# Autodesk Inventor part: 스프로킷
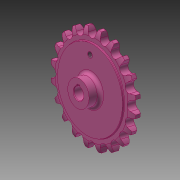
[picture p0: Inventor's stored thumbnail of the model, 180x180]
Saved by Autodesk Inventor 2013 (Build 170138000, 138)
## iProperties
Created: 2016-03
Part Number: 스프로킷
Material: 강철, 탄소
Document SubType Name: Modeling
Designer: mduedu
Density: 7.87 g/cm^3
Mass: 371.373 g
Surface Area: 144.258 cm^2
Volume: 47.1885 cm^3
Author: mduedu
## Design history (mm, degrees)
sketch "스케치1"
  geometry: L1 (0, 5)-(33.5, 5); L2 (33.5, 5)-(33.5, 4.1); L3 (34, 3.6)-(37.625, 3.6); L4 (44, 2)-(44, 0); L5 (44, 0)-(0, 0); L6 (0, 0)-(0, 5); L7 (0, -5)-(33.5, -5); L8 (33.5, -5)-(33.5, -4.1); L9 (34, -3.6)-(37.625, -3.6); L10 (44, -2)-(44, 0); L11 (0, 0)-(0, -5); A1 r 13.5 centre (37.625, -9.9) between (44, 2) and (37.625, 3.6); A2 r 13.5 centre (37.625, 9.9) between (37.625, -3.6) and (44, -2); A3 r 0.5 centre (34, 4.1) between (33.5, 4.1) and (34, 3.6); A4 r 0.5 centre (34, -4.1) between (34, -3.6) and (33.5, -4.1); 2 further points
  constraints: 22 end point, 8 point on circle, 6 symmetric about line, 5 tangent, 4 centre point, 4 parallel, 4 point on line, 1 equal radius, 1 horizontal, 1 perpendicular, 1 other
  dimensions: "d0" = 88 diameter of L4 L6; "d2" = 67 diameter of L2 L6; "d3" = 1.6 vertical distance of L4.start L3.end; "d4" = 3.6 distance from line of L4.end L3; "d5" = 5 distance between parallel lines of L5 L1; "d6" = 13.5 radius of A1; "d15" = 0.5 radius of A3
revolve "회전1" sketch "스케치1" stored, may be unused: angle "d7" = 90 deg
sketch "스케치2" dims "d8" = 73.23, "d11" = 88
  geometry: L1 (0, 0)-(0, 36.615); A1 r 40.59 centre (0, 0) between (-16.319, 37.165) and (0, 40.59); A2 r 3.975 centre (0, 40.59) between (-3.89, 39.774) and (0, 36.615); A3 r 12.7 centre (-16.319, 37.165) between (-3.89, 39.774) and (-5.41, 43.666); A4 r 12.7 centre (16.319, 37.165) between (5.41, 43.666) and (3.89, 39.774); A5 r 3.975 centre (0, 40.59) between (0, 36.615) and (3.89, 39.774); A6 r 44 centre (0, 0) between (5.41, 43.666) and (-5.41, 43.666); 2 further points
  constraints: 12 point on circle, 6 centre point, 4 coincident, 3 symmetric about line, 2 end point, 1 point on line, 1 tangent, 1 vertical, 1 vertical alignment, 7 other
  dimensions: "d10" = 81.18 diameter of A1; "d12" = 12.7 radius of A3
extrude "돌출1" cut sketch "스케치2" stored distance "d13" = 10; taper "d14" = 0 deg
sketch "스케치3"
  geometry: C1 r 11 at (0, 0); 1 further point
  constraints: 1 centre point, 1 coincident
  dimensions: "d19" = 22 diameter of C1
extrude "돌출2" join sketch "스케치3" distance "d20" = 10; taper "d21" = 0 deg
sketch "스케치4"
  geometry: L1 (-1.5, 0)-(1.5, 0); L2 (1.5, 0)-(1.5, 6.4); L3 (1.5, 6.4)-(-1.5, 6.4); L4 (-1.5, 6.4)-(-1.5, 0); C1 r 5 at (0, 0); 2 further points
  constraints: 8 end point, 2 coincident, 2 parallel, 1 centre point, 1 horizontal, 1 midpoint, 1 perpendicular
  dimensions: "d23" = 10 diameter of C1; "d25" = 3 distance of L2.end L3.end; "d26" = 6.4 distance of L1.end L2.end
extrude "돌출3" cut sketch "스케치4" stored distance "d27" = 8; taper "d28" = 0 deg
fillet "모깎기1" dims "d22" = 3
chamfer "모따기1" distance "d29" = 0.5; stored, may be unused: second distance "d30" = 2, angle "d31" = 45 deg
sketch "스케치6" dims "d46" = 50
  geometry: 3 further points
  constraints: 2 vertical alignment, 1 coincident, 2 other
hole "구멍2" sketch "스케치6" at (0, 25) diameter "d48" = 4.917; stored, may be unused: countersink angle "d52" = 90 deg, drill point angle "d54" = 118 deg; dims "d49" = 6, "d50" = 4, "d51" = 2, "d53" = 8
node "솔리드1"
pattern_circular "원형 패턴1" dims angle "d17" = 360 deg
